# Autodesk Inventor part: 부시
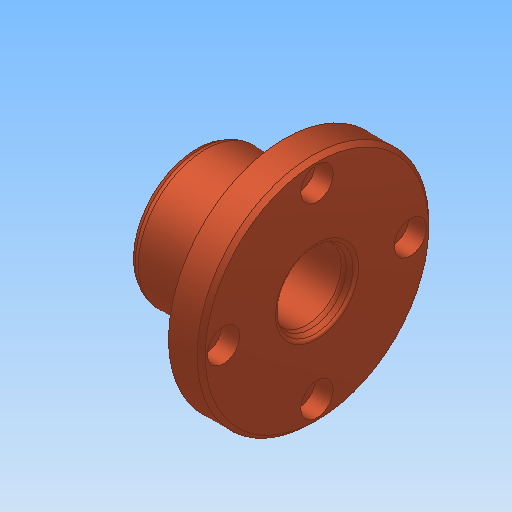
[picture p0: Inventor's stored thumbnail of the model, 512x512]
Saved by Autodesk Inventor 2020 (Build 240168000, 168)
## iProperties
Created: 2024-09
Part Number: 부시
Material: 구리, 합금
Document SubType Name: Modeling
Designer: oem
Density: 8.92 g/cm^3
Appearance: 기본값
Author: jhkim
Sending System: Autodesk Inventor 2025
Preprocessor: ST-DEVELOPER v20
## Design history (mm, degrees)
feature "솔리드1"
node "솔리드2"
